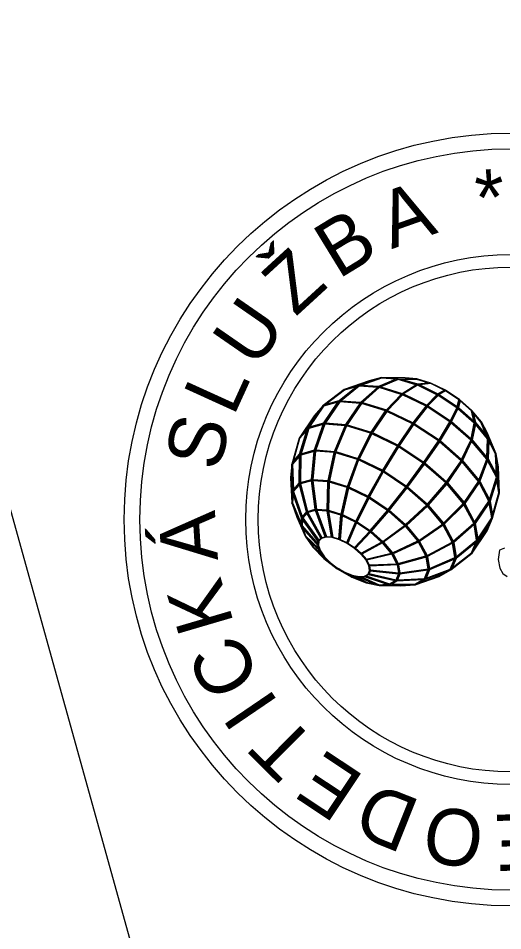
# Model space of a CAD drawing. Extents: x -821057 to -820632, y -1070881 to -1069829.
# Drawn here: x -820969.14 to -820964.31, y -1069882.64 to -1069873.53 of the extents above; entities that cross this region are included whole.
import ezdxf

# ---------------------------------------------------------------- set-up
doc = ezdxf.new("R2010")
doc.units = 0
doc.layers.add('Popisove_pole', color=7, linetype='Continuous')

msp = doc.modelspace()

# ---------------------------------------------------------------- linework, layer by layer
at = {"layer": 'Popisove_pole'}
for p, q in [((-820952.4507, -1069938.7874), (-820975.2073, -1069856.8903)), ((-820965.6425, -1069877.153), (-820965.892, -1069877.2396)), ((-820966.1302, -1069878.8442), (-820966.2838, -1069878.6971)), ((-820966.0903, -1069878.9023), (-820966.2071, -1069878.8087)), ((-820966.033, -1069878.9606), (-820966.0972, -1069878.9205)), ((-820965.9634, -1069879.0138), (-820965.9637, -1069879.0225)), ((-820965.8878, -1069879.0572), (-820965.8186, -1069879.1058)), ((-820965.8128, -1069879.0869), (-820965.6747, -1069879.1629)), ((-820965.7452, -1069879.1004), (-820965.5449, -1069879.1888))]:
    msp.add_line(p, q, dxfattribs=at)
for points in [[(-820965.8186, -1069879.1058), (-820965.6747, -1069879.1629), (-820965.5449, -1069879.1888), (-820965.3319, -1069879.1933), (-820965.1861, -1069879.1825), (-820964.9479, -1069879.1006), (-820964.831, -1069879.0323), (-820964.6181, -1069878.8677), (-820964.4676, -1069878.6451), (-820964.4155, -1069878.5172), (-820964.3437, -1069878.2652), (-820964.3566, -1069878.0041), (-820964.3776, -1069877.8743), (-820964.468, -1069877.6622), (-820964.5252, -1069877.5545), (-820964.6196, -1069877.4416), (-820964.7427, -1069877.3334), (-820964.8835, -1069877.2397), (-820965.0296, -1069877.1687), (-820965.1681, -1069877.1268), (-820965.2865, -1069877.1176), (-820965.5218, -1069877.1129), (-820965.6446, -1069877.1471), (-820965.894, -1069877.2337), (-820966.1024, -1069877.3947), (-820966.1931, -1069877.497), (-820966.3436, -1069877.7195), (-820966.4167, -1069877.9772), (-820966.4281, -1069878.1157), (-820966.4159, -1069878.3642), (-820966.3648, -1069878.506), (-820966.2838, -1069878.6971), (-820966.2071, -1069878.8087), (-820966.0972, -1069878.9205), (-820965.9637, -1069879.0225)], [(-820965.5209, -1069877.1193), (-820965.7163, -1069877.1886), (-820965.548, -1069877.2017), (-820965.3819, -1069877.13)], [(-820965.3559, -1069877.1324), (-820965.5288, -1069877.207), (-820965.315, -1069877.2718), (-820965.1778, -1069877.1864)], [(-820965.169, -1069877.133), (-820965.3133, -1069877.1322), (-820965.1622, -1069877.178), (-820965.0601, -1069877.166)], [(-820965.1408, -1069877.1881), (-820964.9588, -1069877.2766), (-820964.8968, -1069877.2402), (-820965.0307, -1069877.1751)], [(-820966.0734, -1069877.3802), (-820965.9445, -1069877.3444), (-820965.7737, -1069877.2067), (-820965.8912, -1069877.2393)], [(-820965.7442, -1069877.199), (-820965.9254, -1069877.345), (-820965.727, -1069877.3604), (-820965.5621, -1069877.2131)], [(-820965.5454, -1069877.215), (-820965.7123, -1069877.3641), (-820965.4733, -1069877.4365), (-820965.3256, -1069877.2816)], [(-820965.1624, -1069877.1915), (-820965.3012, -1069877.2779), (-820965.0696, -1069877.3904), (-820964.9689, -1069877.2855)], [(-820964.8837, -1069877.2471), (-820964.9467, -1069877.284), (-820964.7656, -1069877.4045), (-820964.7497, -1069877.3362)], [(-820966.2383, -1069877.6067), (-820966.096, -1069877.5672), (-820965.9563, -1069877.3606), (-820966.0985, -1069877.4001)], [(-820966.0809, -1069877.5672), (-820965.8785, -1069877.5829), (-820965.736, -1069877.3722), (-820965.9384, -1069877.3566)], [(-820965.3127, -1069877.2862), (-820965.461, -1069877.4417), (-820965.2057, -1069877.5658), (-820965.0779, -1069877.4003)], [(-820964.9576, -1069877.2917), (-820965.0585, -1069877.397), (-820964.8337, -1069877.5466), (-820964.7696, -1069877.4168)], [(-820964.7389, -1069877.345), (-820964.7546, -1069877.4124), (-820964.6003, -1069877.5481), (-820964.6252, -1069877.445)], [(-820965.8654, -1069877.5859), (-820965.6245, -1069877.6589), (-820965.4813, -1069877.4472), (-820965.7222, -1069877.3742)], [(-820965.6127, -1069877.6637), (-820965.3565, -1069877.7882), (-820965.2131, -1069877.5761), (-820965.4692, -1069877.4516)], [(-820965.0668, -1069877.4065), (-820965.1948, -1069877.5721), (-820964.9479, -1069877.7364), (-820964.8397, -1069877.5576)], [(-820964.7596, -1069877.4247), (-820964.8235, -1069877.5542), (-820964.6281, -1069877.7258), (-820964.5964, -1069877.5681)], [(-820966.285, -1069877.644), (-820966.2579, -1069877.6135), (-820966.161, -1069877.4702), (-820966.1882, -1069877.5008)], [(-820964.6072, -1069877.4661), (-820964.5838, -1069877.5629), (-820964.478, -1069877.6896), (-820964.5307, -1069877.5578)], [(-820966.3241, -1069877.8742), (-820966.1904, -1069877.837), (-820966.1019, -1069877.5818), (-820966.248, -1069877.6224)], [(-820966.0878, -1069877.5792), (-820966.177, -1069877.8366), (-820965.9904, -1069877.851), (-820965.8844, -1069877.595)], [(-820965.9779, -1069877.8536), (-820965.7567, -1069877.9207), (-820965.6308, -1069877.67), (-820965.8717, -1069877.597)], [(-820965.3457, -1069877.7944), (-820965.0982, -1069877.9591), (-820964.9547, -1069877.7469), (-820965.2021, -1069877.5822)], [(-820964.8297, -1069877.5653), (-820964.9379, -1069877.744), (-820964.7227, -1069877.933), (-820964.6318, -1069877.7393)], [(-820964.586, -1069877.5798), (-820964.6174, -1069877.736), (-820964.471, -1069877.9112), (-820964.464, -1069877.7259)], [(-820966.4032, -1069877.9526), (-820966.3389, -1069877.8802), (-820966.2672, -1069877.6427), (-820966.338, -1069877.7226)], [(-820965.745, -1069877.9253), (-820965.51, -1069878.0395), (-820965.3633, -1069877.7988), (-820965.6191, -1069877.6745)], [(-820964.4767, -1069877.6591), (-820964.452, -1069877.7211), (-820964.4405, -1069877.7426), (-820964.4736, -1069877.6649)], [(-820965.3524, -1069877.805), (-820965.4991, -1069878.0458), (-820965.2721, -1069878.1968), (-820965.1054, -1069877.9693)], [(-820964.9447, -1069877.7546), (-820965.0882, -1069877.9667), (-820964.8723, -1069878.1564), (-820964.7289, -1069877.9442)], [(-820964.6227, -1069877.7492), (-820964.7133, -1069877.9422), (-820964.55, -1069878.1377), (-820964.4725, -1069877.9289)], [(-820964.4523, -1069877.7471), (-820964.4591, -1069877.9262), (-820964.3763, -1069878.082), (-820964.3838, -1069877.8759)], [(-820966.4007, -1069878.2334), (-820966.3434, -1069878.1687), (-820966.3398, -1069877.9), (-820966.4103, -1069877.9795)], [(-820966.3308, -1069878.1629), (-820966.2201, -1069878.1321), (-820966.1926, -1069877.8507), (-820966.3272, -1069877.888)], [(-820966.1799, -1069877.8489), (-820966.2075, -1069878.1313), (-820966.0538, -1069878.1432), (-820965.9939, -1069877.8633)], [(-820965.9816, -1069877.8656), (-820966.0415, -1069878.1455), (-820965.8592, -1069878.2008), (-820965.7616, -1069877.9323)], [(-820965.7499, -1069877.9369), (-820965.8475, -1069878.2053), (-820965.6537, -1069878.2995), (-820965.5162, -1069878.0504)], [(-820965.0955, -1069877.977), (-820965.2621, -1069878.2044), (-820965.0641, -1069878.3784), (-820964.8799, -1069878.1663)], [(-820964.7201, -1069877.9536), (-820964.8633, -1069878.1653), (-820964.6989, -1069878.3621), (-820964.5557, -1069878.1504)], [(-820964.4644, -1069877.9429), (-820964.541, -1069878.1495), (-820964.4446, -1069878.331), (-820964.3758, -1069878.1095)], [(-820964.3677, -1069877.9744), (-820964.3628, -1069878.1083), (-820964.3555, -1069878.1538), (-820964.3628, -1069878.0048)], [(-820966.4143, -1069878.269), (-820966.4127, -1069878.249), (-820966.419, -1069878.0813), (-820966.4218, -1069878.1158)], [(-820965.5054, -1069878.0566), (-820965.6428, -1069878.3057), (-820965.4555, -1069878.4303), (-820965.2797, -1069878.2068)], [(-820966.2596, -1069878.4498), (-820966.1831, -1069878.4286), (-820966.2196, -1069878.145), (-820966.3296, -1069878.1755)], [(-820966.2072, -1069878.1438), (-820966.1706, -1069878.4273), (-820966.0638, -1069878.4356), (-820966.0553, -1069878.1556)], [(-820966.0428, -1069878.1582), (-820966.0514, -1069878.4377), (-820965.9239, -1069878.4763), (-820965.8627, -1069878.2127)], [(-820964.8712, -1069878.1754), (-820965.0553, -1069878.3874), (-820964.9043, -1069878.5681), (-820964.7069, -1069878.3721)], [(-820964.5485, -1069878.1621), (-820964.6911, -1069878.3729), (-820964.5929, -1069878.5576), (-820964.4503, -1069878.3468)], [(-820964.371, -1069878.1361), (-820964.4367, -1069878.3476), (-820964.4138, -1069878.4885), (-820964.3501, -1069878.2648)], [(-820966.3112, -1069878.5013), (-820966.2709, -1069878.4559), (-820966.3403, -1069878.1841), (-820966.3993, -1069878.2506)], [(-820965.851, -1069878.2175), (-820965.9121, -1069878.4808), (-820965.7761, -1069878.5469), (-820965.6595, -1069878.3106)], [(-820965.2697, -1069878.2144), (-820965.4456, -1069878.4379), (-820965.2822, -1069878.5815), (-820965.0728, -1069878.3874)], [(-820966.3244, -1069878.5694), (-820966.3199, -1069878.5142), (-820966.4026, -1069878.2789), (-820966.4095, -1069878.3632)], [(-820965.6486, -1069878.3168), (-820965.7652, -1069878.5531), (-820965.6335, -1069878.6407), (-820965.4635, -1069878.44)], [(-820966.2548, -1069878.4615), (-820966.1168, -1069878.712), (-820966.0824, -1069878.7024), (-820966.18, -1069878.4407)], [(-820966.1669, -1069878.4401), (-820966.0697, -1069878.7007), (-820966.0199, -1069878.7046), (-820966.0631, -1069878.4482)], [(-820966.0499, -1069878.4512), (-820966.0069, -1069878.7065), (-820965.9459, -1069878.725), (-820965.926, -1069878.4888)], [(-820965.4535, -1069878.4476), (-820965.6236, -1069878.6483), (-820965.5089, -1069878.7491), (-820965.2921, -1069878.5895)], [(-820965.0641, -1069878.3963), (-820965.2735, -1069878.5904), (-820965.1491, -1069878.7394), (-820964.9139, -1069878.5761)], [(-820964.7, -1069878.3829), (-820964.897, -1069878.5785), (-820964.8066, -1069878.7486), (-820964.6014, -1069878.5683)], [(-820964.4467, -1069878.3637), (-820964.587, -1069878.5711), (-820964.5624, -1069878.7232), (-820964.4221, -1069878.5158)], [(-820966.3139, -1069878.5936), (-820966.1543, -1069878.7761), (-820966.1521, -1069878.7502), (-820966.3087, -1069878.5309)], [(-820966.1452, -1069878.7384), (-820966.1275, -1069878.7185), (-820966.2652, -1069878.4683), (-820966.3056, -1069878.5138)], [(-820965.9139, -1069878.4939), (-820965.9337, -1069878.7295), (-820965.8673, -1069878.7618), (-820965.7813, -1069878.5583)], [(-820966.1451, -1069878.8213), (-820966.1547, -1069878.7945), (-820966.3032, -1069878.6248), (-820966.2784, -1069878.6936)], [(-820965.7704, -1069878.5646), (-820965.8564, -1069878.7679), (-820965.7917, -1069878.811), (-820965.642, -1069878.6501)], [(-820965.2831, -1069878.5984), (-820965.5002, -1069878.7582), (-820965.4132, -1069878.8624), (-820965.1602, -1069878.7455)], [(-820964.907, -1069878.5865), (-820965.1421, -1069878.7497), (-820965.0676, -1069878.8899), (-820964.8169, -1069878.7559)], [(-820964.5979, -1069878.5819), (-820964.8017, -1069878.7609), (-820964.7786, -1069878.9032), (-820964.5728, -1069878.7372)], [(-820964.4439, -1069878.5704), (-820964.5605, -1069878.7427), (-820964.5897, -1069878.8144), (-820964.4732, -1069878.6421)], [(-820965.7266, -1069878.8754), (-820965.7907, -1069878.8191), (-820965.8642, -1069878.7703), (-820965.9403, -1069878.7333), (-820966.0124, -1069878.7114), (-820966.0741, -1069878.7066), (-820966.1199, -1069878.7193), (-820966.1457, -1069878.7484), (-820966.1493, -1069878.7913), (-820966.1302, -1069878.8442), (-820966.0903, -1069878.9023), (-820966.033, -1069878.9606), (-820965.9634, -1069879.0138), (-820965.8878, -1069879.0572), (-820965.8128, -1069879.0869), (-820965.7452, -1069879.1004), (-820965.6908, -1069879.0964), (-820965.6546, -1069879.0752), (-820965.6398, -1069879.0388), (-820965.6476, -1069878.9904), (-820965.6774, -1069878.9343)], [(-820965.7818, -1069878.8186), (-820965.7258, -1069878.8679), (-820965.5201, -1069878.7559), (-820965.6319, -1069878.6577)], [(-820966.1194, -1069878.871), (-820966.135, -1069878.8482), (-820966.2442, -1069878.7436), (-820966.2025, -1069878.8044)], [(-820965.7169, -1069878.8773), (-820965.6751, -1069878.9273), (-820965.4262, -1069878.8664), (-820965.5108, -1069878.7651)], [(-820965.4063, -1069878.873), (-820965.3545, -1069878.9704), (-820965.0794, -1069878.8944), (-820965.153, -1069878.7559)], [(-820964.8132, -1069878.7682), (-820965.0633, -1069878.9017), (-820965.0443, -1069879.0193), (-820964.79, -1069878.911)], [(-820964.5809, -1069878.7599), (-820964.7779, -1069878.9187), (-820964.8164, -1069879.0132), (-820964.6233, -1069878.8637)], [(-820966.0932, -1069878.9156), (-820966.0745, -1069878.9273), (-820966.0945, -1069878.907), (-820966.1286, -1069878.8796)], [(-820965.4182, -1069878.8773), (-820965.6682, -1069878.9385), (-820965.6439, -1069878.984), (-820965.3679, -1069878.972)], [(-820965.0752, -1069878.9062), (-820965.3506, -1069878.9823), (-820965.3374, -1069879.0636), (-820965.0563, -1069879.0229)], [(-820965.6403, -1069878.9964), (-820965.6344, -1069879.0331), (-820965.3501, -1069879.0636), (-820965.363, -1069878.9843)], [(-820964.7946, -1069878.9265), (-820965.0443, -1069879.0329), (-820965.0778, -1069879.1151), (-820964.8357, -1069879.0274)], [(-820965.964, -1069879.0145), (-820965.9696, -1069879.0102)], [(-820965.9476, -1069879.0246), (-820965.9333, -1069879.0328)], [(-820965.765, -1069879.1204), (-820965.8155, -1069879.0926), (-820965.8409, -1069879.0825), (-820965.8156, -1069879.1003)], [(-820965.3879, -1069879.1431), (-820965.6536, -1069879.0819), (-820965.6758, -1069879.0949), (-820965.4413, -1069879.1743)], [(-820965.3516, -1069879.076), (-820965.6358, -1069879.0456), (-820965.646, -1069879.0708), (-820965.3749, -1069879.1332)], [(-820965.0591, -1069879.0359), (-820965.3382, -1069879.0763), (-820965.3616, -1069879.1338), (-820965.0932, -1069879.1198)], [(-820964.8936, -1069879.0617), (-820965.0863, -1069879.1315), (-820965.1284, -1069879.1561), (-820964.9505, -1069879.0949)], [(-820965.5994, -1069879.1716), (-820965.747, -1069879.1064), (-820965.7744, -1069879.1009), (-820965.6726, -1069879.157)], [(-820965.4718, -1069879.1771), (-820965.6916, -1069879.1027), (-820965.7197, -1069879.1048), (-820965.5438, -1069879.1824)], [(-820965.1143, -1069879.1334), (-820965.3693, -1069879.1467), (-820965.4177, -1069879.175), (-820965.1877, -1069879.1763)]]:
    msp.add_lwpolyline(points, close=True, dxfattribs=at)
for points in [[(-820966.0741, -1069878.7066), (-820966.1762, -1069878.4331), (-820966.2143, -1069878.137), (-820966.1855, -1069877.8422), (-820966.0921, -1069877.5726), (-820965.9416, -1069877.35), (-820965.7462, -1069877.1926), (-820965.5218, -1069877.1129)], [(-820966.0124, -1069878.7114), (-820966.0578, -1069878.4423), (-820966.0488, -1069878.1498), (-820965.9863, -1069877.8576), (-820965.8753, -1069877.5894), (-820965.7248, -1069877.3668), (-820965.547, -1069877.208), (-820965.3562, -1069877.1258), (-820965.1681, -1069877.1268)], [(-820965.9403, -1069878.7333), (-820965.9194, -1069878.4843), (-820965.8553, -1069878.2085), (-820965.7534, -1069877.9282), (-820965.6219, -1069877.6662), (-820965.4714, -1069877.4436), (-820965.3141, -1069877.2786), (-820965.1628, -1069877.1844), (-820965.0296, -1069877.1687)], [(-820964.3776, -1069877.8743), (-820964.4576, -1069877.7237), (-820964.5895, -1069877.5658), (-820964.7616, -1069877.4147), (-820964.9585, -1069877.2836), (-820965.1628, -1069877.1844), (-820965.3562, -1069877.1258), (-820965.5218, -1069877.1129)], [(-820964.3437, -1069878.2652), (-820964.3691, -1069878.1089), (-820964.4654, -1069877.9277), (-820964.6242, -1069877.7377), (-820964.8312, -1069877.5557), (-820965.0682, -1069877.398), (-820965.3141, -1069877.2786), (-820965.547, -1069877.208), (-820965.7462, -1069877.1926), (-820965.894, -1069877.2337)], [(-820965.8642, -1069878.7703), (-820965.7732, -1069878.5553), (-820965.6511, -1069878.3077), (-820965.5076, -1069878.0476), (-820965.3544, -1069877.7962), (-820965.2038, -1069877.5736), (-820965.0682, -1069877.398), (-820964.9585, -1069877.2836), (-820964.8835, -1069877.2397)], [(-820964.4155, -1069878.5172), (-820964.4431, -1069878.3471), (-820964.5479, -1069878.15), (-820964.7206, -1069877.9432), (-820964.946, -1069877.7452), (-820965.2038, -1069877.5736), (-820965.4714, -1069877.4436), (-820965.7248, -1069877.3668), (-820965.9416, -1069877.35), (-820966.1024, -1069877.3947)], [(-820965.7907, -1069878.8191), (-820965.6324, -1069878.649), (-820965.4542, -1069878.4387), (-820965.2706, -1069878.2053), (-820965.0965, -1069877.9678), (-820964.946, -1069877.7452), (-820964.8312, -1069877.5557), (-820964.7616, -1069877.4147), (-820964.7427, -1069877.3334)], [(-820966.1199, -1069878.7193), (-820966.264, -1069878.4576), (-820966.3372, -1069878.1711), (-820966.3334, -1069877.8833), (-820966.2529, -1069877.6173), (-820966.1024, -1069877.3947)], [(-820965.7266, -1069878.8754), (-820965.5093, -1069878.7571), (-820965.2821, -1069878.5899), (-820965.0635, -1069878.3873), (-820964.8711, -1069878.1657), (-820964.7206, -1069877.9432), (-820964.6242, -1069877.7377), (-820964.5895, -1069877.5658), (-820964.6196, -1069877.4416)], [(-820964.6181, -1069878.8677), (-820964.566, -1069878.7398), (-820964.5936, -1069878.5697), (-820964.6984, -1069878.3725), (-820964.8711, -1069878.1657), (-820965.0965, -1069877.9678), (-820965.3544, -1069877.7962), (-820965.6219, -1069877.6662), (-820965.8753, -1069877.5894), (-820966.0921, -1069877.5726), (-820966.2529, -1069877.6173), (-820966.3436, -1069877.7195)], [(-820965.6774, -1069878.9343), (-820965.4149, -1069878.8701), (-820965.1502, -1069878.7478), (-820964.9047, -1069878.5773), (-820964.6984, -1069878.3725), (-820964.5479, -1069878.15), (-820964.4654, -1069877.9277), (-820964.4576, -1069877.7237), (-820964.5252, -1069877.5545)], [(-820964.831, -1069879.0323), (-820964.7831, -1069878.9148), (-820964.8084, -1069878.7585), (-820964.9047, -1069878.5773), (-820965.0635, -1069878.3873), (-820965.2706, -1069878.2053), (-820965.5076, -1069878.0476), (-820965.7534, -1069877.9282), (-820965.9863, -1069877.8576), (-820966.1855, -1069877.8422), (-820966.3334, -1069877.8833), (-820966.4167, -1069877.9772)], [(-820965.6476, -1069878.9904), (-820965.3577, -1069878.9778), (-820965.0702, -1069878.8983), (-820964.8084, -1069878.7585), (-820964.5936, -1069878.5697), (-820964.4431, -1069878.3471), (-820964.3691, -1069878.1089), (-820964.3776, -1069877.8743)], [(-820966.1457, -1069878.7484), (-820966.3136, -1069878.5134), (-820966.4064, -1069878.2492), (-820966.4167, -1069877.9772)], [(-820965.1861, -1069879.1825), (-820965.0889, -1069879.1258), (-820965.0491, -1069879.0282), (-820965.0702, -1069878.8983), (-820965.1502, -1069878.7478), (-820965.2821, -1069878.5899), (-820965.4542, -1069878.4387), (-820965.6511, -1069878.3077), (-820965.8553, -1069878.2085), (-820966.0488, -1069878.1498), (-820966.2143, -1069878.137), (-820966.3372, -1069878.1711), (-820966.4064, -1069878.2492), (-820966.4159, -1069878.3642)], [(-820966.1493, -1069878.7913), (-820966.3203, -1069878.5957), (-820966.4159, -1069878.3642)], [(-820965.5449, -1069879.1888), (-820965.4406, -1069879.1811), (-820965.3711, -1069879.1405), (-820965.3426, -1069879.0707), (-820965.3577, -1069878.9778), (-820965.4149, -1069878.8701), (-820965.5093, -1069878.7571), (-820965.6324, -1069878.649), (-820965.7732, -1069878.5553), (-820965.9194, -1069878.4843), (-820966.0578, -1069878.4423), (-820966.1762, -1069878.4331), (-820966.264, -1069878.4576), (-820966.3136, -1069878.5134), (-820966.3203, -1069878.5957), (-820966.2838, -1069878.6971)], [(-820965.6398, -1069879.0388), (-820965.3426, -1069879.0707), (-820965.0491, -1069879.0282), (-820964.7831, -1069878.9148), (-820964.566, -1069878.7398), (-820964.4155, -1069878.5172)], [(-820964.2968, -1069878.8183), (-820964.3451, -1069878.8386), (-820964.3591, -1069878.9296), (-820964.3414, -1069879.0161), (-820964.3134, -1069879.0699), (-820964.2683, -1069879.0994)], [(-820965.6546, -1069879.0752), (-820965.3711, -1069879.1405), (-820965.0889, -1069879.1258), (-820964.831, -1069879.0323)], [(-820965.6908, -1069879.0964), (-820965.4406, -1069879.1811), (-820965.1861, -1069879.1825)]]:
    msp.add_lwpolyline(points, dxfattribs=at)
for radius in [3.8563, 3.7, 3.7, 2.6447, 2.6447, 2.5197]:
    msp.add_circle((-820964.2313, -1069878.531), radius, dxfattribs=at)

# ---------------------------------------------------------------- texts
for s, rotation, p in [('*', 2.51854, (-820964.579, -1069875.6031)), ('A', 19.54539, (-820965.4211, -1069875.8332)), ('B', 31.4663, (-820965.9527, -1069876.1372)), ('Ž', 42.5327, (-820966.3802, -1069876.5121)), ('U', 55.29757, (-820966.7731, -1069877.0368)), ('L', 65.52001, (-820966.9979, -1069877.5116)), ('S', 76.58641, (-820967.1422, -1069878.0616)), ('Á', 93.61327, (-820967.152, -1069878.9346)), ('K', 106.37813, (-820966.9906, -1069879.5699)), ('C', 118.29904, (-820966.7165, -1069880.1175)), ('I', 124.25949, (-820966.5383, -1069880.367)), ('T', 135.3259, (-820966.143, -1069880.7757)), ('E', 146.3923, (-820965.6766, -1069881.1009)), ('D', 158.3132, (-820965.1146, -1069881.344)), ('O', 171.07807, (-820964.4712, -1069881.4697)), ('E', 182.14447, (-820963.9027, -1069881.4611))]:
    msp.add_text(s, height=0.5625, rotation=rotation, dxfattribs=at).set_placement(p)

doc.saveas('drawing.dxf')
